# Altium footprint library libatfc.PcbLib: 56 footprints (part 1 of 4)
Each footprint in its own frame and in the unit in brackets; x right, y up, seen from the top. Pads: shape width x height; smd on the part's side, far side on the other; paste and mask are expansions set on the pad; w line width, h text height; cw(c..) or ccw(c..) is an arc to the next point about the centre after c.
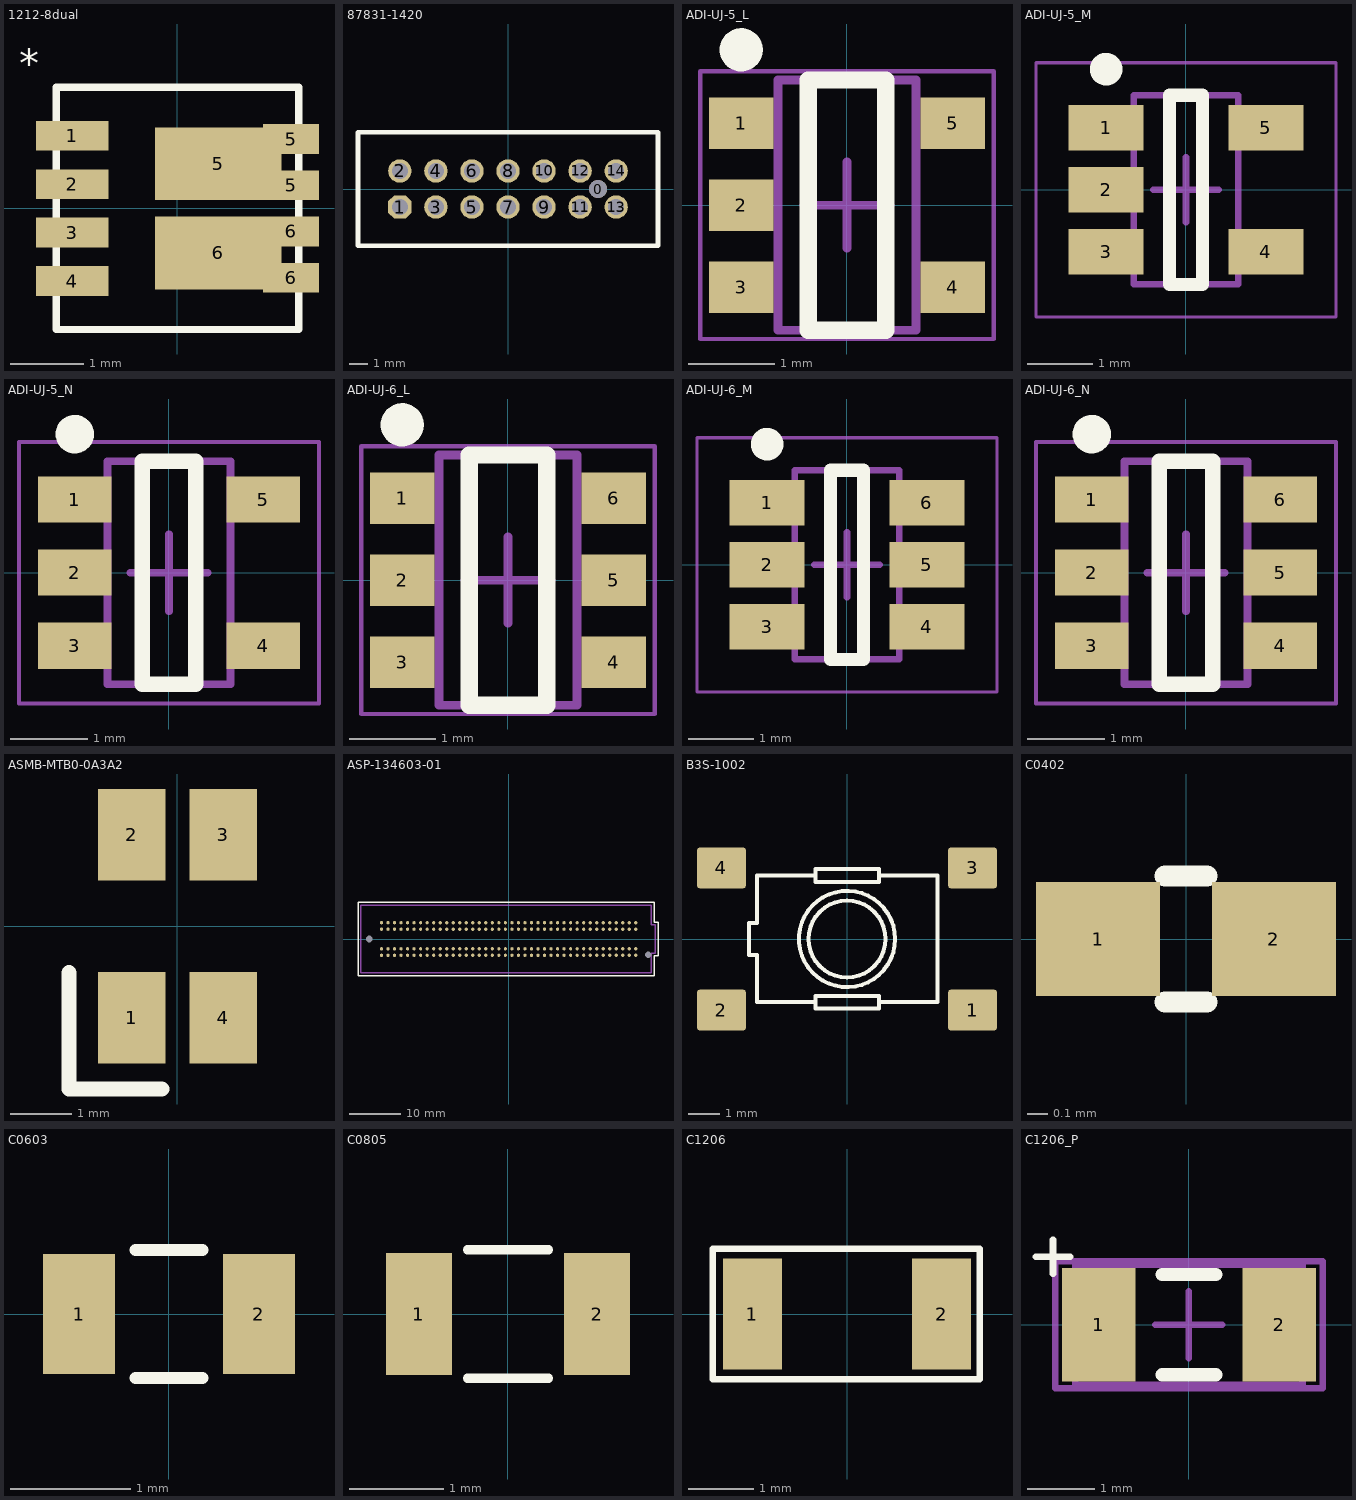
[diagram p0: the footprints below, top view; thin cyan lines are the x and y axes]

## 1212-8dual [mm]
pads (10):
  rect 0.99x0.405 smd: 1(-1.435,0.99) 2(-1.435,0.33) 3(-1.435,-0.33) 4(-1.435,-0.99)
  rect 1.725x0.99 smd: 5(0.557,0.607) 6(0.557,-0.608)
  rect 0.76x0.405 smd: 5(1.55,0.315) 5(1.55,0.945) 6(1.55,-0.945) 6(1.55,-0.315)
Top Overlay:
  lines w0.1: 1.65,-1.65 -1.65,-1.65 -1.65,1.65 1.65,1.65 ; 1.652,-1.65 1.652,1.65
  text "*" at -2.159,1.778 h0.4
3D body: height 0.5, standoff 0, extent -1.651,-1.651 1.651,1.651

## 87831-1420 [mm] "Molex 2mm 14pin header"
pads (15):
  round 1 hole 1: 0(5,0)
  oct 1.3x1.3 hole 0.9: 1(-6,-1)
  round 1.3 hole 0.9: 2(-6,1) 3(-4,-1) 4(-4,1) 5(-2,-1) 6(-2,1) 7(0,-1) 8(0,1) 9(2,-1) 10(2,1) 11(4,-1) 12(4,1) 13(6,-1) 14(6,1)
Top Overlay:
  lines w0.254: -8.325,-3.15 -8.325,3.15 8.325,3.15 8.325,-3.15 -8.325,-3.15
3D body "878311420.stp": height 6.2, standoff -2.7, extent -8.35,-3.251 8.3,3.049

## ADI-UJ-5_L [mm] "SOT23, 5-Leads, Body 2.9x1.6mm, Pitch 0.95mm, IPC High Density"
height 1
pads (5):
  rect 0.75x0.6 smd: 1(-1.225,0.95) 2(-1.225,0) 3(-1.225,-0.95) 4(1.225,-0.95) 5(1.225,0.95)
Top Overlay:
  circle w0.25: c-1.225,1.8 r0.125
  lines w0.2: -0.45,-1.45 -0.45,1.45 0.45,1.45 0.45,-1.45 -0.45,-1.45
Mechanical 13:
  lines w0.1: -0.8,-1.45 0.8,-1.45 0.8,1.45 -0.8,1.45 -0.8,-1.45
Mechanical 15:
  lines w0.05: -1.7,-1.55 1.7,-1.55 1.7,1.55 -1.7,1.55 -1.7,-1.55
  lines w0.1: -0.5,0 0.5,0 ; 0,-0.5 0,0.5
3D body: height 1, standoff 0, extent -0.8,-1.45 0.8,1.45

## ADI-UJ-5_M [mm] "SOT23, 5-Leads, Body 2.9x1.6mm, Pitch 0.95mm, IPC Low Density"
height 1
pads (5):
  rect 1.15x0.7 smd: 1(-1.225,0.95) 2(-1.225,0) 3(-1.225,-0.95) 4(1.225,-0.95) 5(1.225,0.95)
Top Overlay:
  circle w0.25: c-1.225,1.85 r0.125
  lines w0.2: -0.25,-1.45 0.25,-1.45 0.25,1.45 -0.25,1.45 -0.25,-1.45
Mechanical 13:
  lines w0.1: -0.8,-1.45 -0.8,1.45 0.8,1.45 0.8,-1.45 -0.8,-1.45
Mechanical 15:
  lines w0.05: -2.3,-1.95 -2.3,1.95 2.3,1.95 2.3,-1.95 -2.3,-1.95
  lines w0.1: -0.5,0 0.5,0 ; 0,-0.5 0,0.5
3D body: height 1, standoff 0, extent -0.8,-1.45 0.8,1.45

## ADI-UJ-5_N [mm] "SOT23, 5-Leads, Body 2.9x1.6mm, Pitch 0.95mm, IPC Medium Density"
height 1
pads (5):
  rect 0.95x0.6 smd: 1(-1.225,0.95) 2(-1.225,0) 3(-1.225,-0.95) 4(1.225,-0.95) 5(1.225,0.95)
Top Overlay:
  circle w0.25: c-1.225,1.8 r0.125
  lines w0.2: -0.35,-1.45 -0.35,1.45 0.35,1.45 0.35,-1.45 -0.35,-1.45
Mechanical 13:
  lines w0.1: -0.8,-1.45 0.8,-1.45 0.8,1.45 -0.8,1.45 -0.8,-1.45
Mechanical 15:
  lines w0.05: -1.95,-1.7 1.95,-1.7 1.95,1.7 -1.95,1.7 -1.95,-1.7
  lines w0.1: -0.5,0 0.5,0 ; 0,-0.5 0,0.5
3D body: height 1, standoff 0, extent -0.8,-1.45 0.8,1.45

## ADI-UJ-6_L [mm] "SOT23, 6-Leads, Body 2.9x1.6mm, Pitch 0.95mm, IPC High Density"
height 1
pads (6):
  rect 0.75x0.6 smd: 1(-1.225,0.95) 2(-1.225,0) 3(-1.225,-0.95) 4(1.225,-0.95) 5(1.225,0) 6(1.225,0.95)
Top Overlay:
  circle w0.25: c-1.225,1.8 r0.125
  lines w0.2: -0.45,-1.45 0.45,-1.45 0.45,1.45 -0.45,1.45 -0.45,-1.45
Mechanical 13:
  lines w0.1: -0.8,-1.45 -0.8,1.45 0.8,1.45 0.8,-1.45 -0.8,-1.45
Mechanical 15:
  lines w0.05: -1.7,-1.55 -1.7,1.55 1.7,1.55 1.7,-1.55 -1.7,-1.55
  lines w0.1: -0.5,0 0.5,0 ; 0,-0.5 0,0.5
3D body: height 1, standoff 0.1, extent -0.8,-1.45 0.8,1.45

## ADI-UJ-6_M [mm] "SOT23, 6-Leads, Body 2.9x1.6mm, Pitch 0.95mm, IPC Low Density"
height 1
pads (6):
  rect 1.15x0.7 smd: 1(-1.225,0.95) 2(-1.225,0) 3(-1.225,-0.95) 4(1.225,-0.95) 5(1.225,0) 6(1.225,0.95)
Top Overlay:
  circle w0.25: c-1.225,1.85 r0.125
  lines w0.2: -0.25,-1.45 0.25,-1.45 0.25,1.45 -0.25,1.45 -0.25,-1.45
Mechanical 13:
  lines w0.1: -0.8,-1.45 -0.8,1.45 0.8,1.45 0.8,-1.45 -0.8,-1.45
Mechanical 15:
  lines w0.05: -2.3,-1.95 -2.3,1.95 2.3,1.95 2.3,-1.95 -2.3,-1.95
  lines w0.1: -0.5,0 0.5,0 ; 0,-0.5 0,0.5
3D body: height 1, standoff 0.1, extent -0.8,-1.45 0.8,1.45

## ADI-UJ-6_N [mm] "SOT23, 6-Leads, Body 2.9x1.6mm, Pitch 0.95mm, IPC Medium Density"
height 1
pads (6):
  rect 0.95x0.6 smd: 1(-1.225,0.95) 2(-1.225,0) 3(-1.225,-0.95) 4(1.225,-0.95) 5(1.225,0) 6(1.225,0.95)
Top Overlay:
  circle w0.25: c-1.225,1.8 r0.125
  lines w0.2: -0.35,-1.45 -0.35,1.45 0.35,1.45 0.35,-1.45 -0.35,-1.45
Mechanical 13:
  lines w0.1: -0.8,-1.45 0.8,-1.45 0.8,1.45 -0.8,1.45 -0.8,-1.45
Mechanical 15:
  lines w0.05: -1.95,-1.7 1.95,-1.7 1.95,1.7 -1.95,1.7 -1.95,-1.7
  lines w0.1: -0.5,0 0.5,0 ; 0,-0.5 0,0.5
3D body: height 1, standoff 0.1, extent -0.8,-1.45 0.8,1.45

## ASMB-MTB0-0A3A2 [mm]
pads (4):
  rect 1.1x1.5 smd: 1(-0.75,-1.5) 2(-0.75,1.5) 3(0.75,1.5) 4(0.75,-1.5)
Top Overlay:
  lines w0.254: -1.778,-0.762 -1.778,-2.667 -0.254,-2.667
3D body "User Library-ASMB-MTB0-0A3A2.STEP": height 1.9, standoff 0, extent -1.395,-1.685 1.405,1.815

## ASP-134603-01 [mil]
pads (162):
  round 25 smd paste+5 mask+2: C1(975,-125) C2(925,-125) C3(875,-125) C4(825,-125) C5(775,-125) C6(725,-125) C7(675,-125) C8(625,-125) C9(575,-125) C10(525,-125) C11(475,-125) C12(425,-125) C13(375,-125) C14(325,-125) C15(275,-125) C16(225,-125) C17(175,-125) C18(125,-125) C19(75,-125) C20(25,-125) C21(-25,-125) C22(-75,-125) C23(-125,-125) C24(-175,-125) C25(-225,-125) C26(-275,-125) C27(-325,-125) C28(-375,-125) C29(-425,-125) C30(-475,-125) C31(-525,-125) C32(-575,-125) C33(-625,-125) C34(-675,-125) C35(-725,-125) C36(-775,-125) C37(-825,-125) C38(-875,-125) C39(-925,-125) C40(-975,-125) D1(975,-75) D2(925,-75) D3(875,-75) D4(825,-75) D5(775,-75) D6(725,-75) D7(675,-75) D8(625,-75) D9(575,-75) D10(525,-75) D11(475,-75) D12(425,-75) D13(375,-75) D14(325,-75) D15(275,-75) D16(225,-75) D17(175,-75) D18(125,-75) D19(75,-75) D20(25,-75) D21(-25,-75) D22(-75,-75) D23(-125,-75) D24(-175,-75) D25(-225,-75) D26(-275,-75) D27(-325,-75) D28(-375,-75) D29(-425,-75) D30(-475,-75) D31(-525,-75) D32(-575,-75) D33(-625,-75) D34(-675,-75) D35(-725,-75) D36(-775,-75) D37(-825,-75) D38(-875,-75) D39(-925,-75) D40(-975,-75) G1(975,75) G2(925,75) G3(875,75) G4(825,75) G5(775,75) G6(725,75) G7(675,75) G8(625,75) G9(575,75) G10(525,75) G11(475,75) G12(425,75) G13(375,75) G14(325,75) G15(275,75) G16(225,75) G17(175,75) G18(125,75) G19(75,75) G20(25,75) G21(-25,75) G22(-75,75) G23(-125,75) G24(-175,75) G25(-225,75) G26(-275,75) G27(-325,75) G28(-375,75) G29(-425,75) G30(-475,75) G31(-525,75) G32(-575,75) G33(-625,75) G34(-675,75) G35(-725,75) G36(-775,75) G37(-825,75) G38(-875,75) G39(-925,75) G40(-975,75) H1(975,125) H2(925,125) H3(875,125) H4(825,125) H5(775,125) H6(725,125) H7(675,125) H8(625,125) H9(575,125) H10(525,125) H11(475,125) H12(425,125) H13(375,125) H14(325,125) H15(275,125) H16(225,125) H17(175,125) H18(125,125) H19(75,125) H20(25,125) H21(-25,125) H22(-75,125) H23(-125,125) H24(-175,125) H25(-225,125) H26(-275,125) H27(-325,125) H28(-375,125) H29(-425,125) H30(-475,125) H31(-525,125) H32(-575,125) H33(-625,125) H34(-675,125) H35(-725,125) H36(-775,125) H37(-825,125) H38(-875,125) H39(-925,125) H40(-975,125)
  round 0 hole 50 unplated: MH1(1070.5,-120) MH2(-1070.5,0)
Top Overlay:
  lines w10: -1155,-280 1115,-280 1115,-130 1145,-130 1145,130 1115,130 1115,280 -1155,280 -1155,-280
Mechanical 1:
  lines w10: -1135,-260 1095,-260 1095,-110 1125,-110 1125,110 1095,110 1095,260 -1135,260 -1135,-260
  text "J1" at -19.57,-20 h30
3D body "459714305.stp": height 259.15, standoff -48.85, extent -1131,-295 1151,283

## B3S-1002 [mm]
height 7.12
pads (4):
  rrect15% 1.55x1.3 smd: 1(3.975,-2.25) 2(-3.975,-2.25) 3(3.975,2.25) 4(-3.975,2.25)
Top Overlay:
  circle w0.127: c0,0 r1.524
  circle w0.127: c0,0 r1.219
  lines w0.127: -1,-2 -1,-1.8 1.016,-1.8 1.016,-2 ; -1,-2 -1,-2.2 1.016,-2.2 1.016,-2 ; -1,-2 -2.85,-2 -2.85,-0.5 -3.1,-0.5 -3.1,0.508 -2.85,0.508 -2.85,2.007 -1,2.007 ; -1,2.007 -1,2.21 1.016,2.21 1.016,2.007 ; -1,2.007 -1,1.803 1.016,1.803 1.016,2.007 ; 1.016,-2 2.87,-2 2.87,2.007 1.016,2.007
3D body "B3S_100[].stp": height 4.4, standoff 0, extent -4.627,-3.327 4.373,3.273

## C0402 [mm]
pads (2):
  rect 0.6x0.55 smd: 1(-0.425,0) 2(0.425,0)
Top Overlay:
  lines w0.102: -0.102,-0.305 0.102,-0.305 ; -0.102,0.305 0.102,0.305
3D body: height 0.35, standoff 0, extent 0.381,-0.254 0.54,0.254
3D body: height 0.35, standoff 0, extent -0.381,-0.254 0.381,0.254
3D body: height 0.35, standoff 0, extent -0.54,-0.254 -0.381,0.254

## C0603 [mm]
pads (2):
  rect 0.6x1 smd: 1(-0.75,0) 2(0.75,0)
Top Overlay:
  lines w0.1: -0.279,-0.533 0.279,-0.533 ; -0.279,0.533 0.279,0.533
3D body: height 0.35, standoff 0, extent -0.508,-0.444 0.508,0.445
3D body: height 0.35, standoff 0, extent 0.508,-0.444 0.762,0.445
3D body: height 0.35, standoff 0, extent -0.762,-0.444 -0.508,0.445

## C0805 [mm]
pads (2):
  rect 0.7x1.3 smd: 1(-0.95,0) 2(0.95,0)
Top Overlay:
  lines w0.1: -0.432,-0.686 0.432,-0.686 ; -0.432,0.686 0.432,0.686
3D body: height 0.35, standoff 0, extent -1.016,-0.603 -0.762,0.603
3D body: height 0.35, standoff 0, extent -0.762,-0.603 0.762,0.603
3D body: height 0.35, standoff 0, extent 0.762,-0.603 1.016,0.603

## C1206 [mm]
pads (2):
  rect 0.9x1.7 smd: 1(-1.45,0) 2(1.45,0)
Top Overlay:
  lines w0.1: -2.057,-1 2.032,-1 2.032,1 -2.057,1 -2.057,0.043 -2.057,-1
3D body: height 0.55, standoff 0, extent 1.016,-0.762 1.524,0.762
3D body: height 0.55, standoff 0, extent -1.016,-0.762 1.016,0.762
3D body: height 0.55, standoff 0, extent -1.524,-0.762 -1.016,0.762

## C1206_P [mm]
height 1.3
pads (2):
  rect 1.1x1.7 smd: 1(-1.35,0) 2(1.35,0)
Top Overlay:
  lines w0.1: -2.286,1.016 -1.778,1.016 ; -2.032,0.762 -2.032,1.27
  lines w0.2: -0.4,-0.75 0.4,-0.75 ; -0.4,0.75 0.4,0.75
Mechanical 13:
  lines w0.1: -1.7,-0.9 1.7,-0.9 1.7,0.9 -1.7,0.9 -1.7,-0.9
Mechanical 15:
  lines w0.1: -0.5,0 0.5,0 ; 0,-0.5 0,0.5 ; -2,-0.95 2,-0.95 2,0.95 -2,0.95 -2,-0.95
3D body: height 1.3, standoff 0, extent -1.7,-0.9 1.7,0.9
